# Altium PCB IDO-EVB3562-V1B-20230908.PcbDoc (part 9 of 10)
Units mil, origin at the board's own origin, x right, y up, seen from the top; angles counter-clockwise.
Board outline 5314.96 x 3543.31 mil, 4 copper layers (TOP, L2-VCC, L3-GND, BOTTOM), stack 28.8 mil thick; 747 components, 560 nets, 2514 pads, 1964 vias.
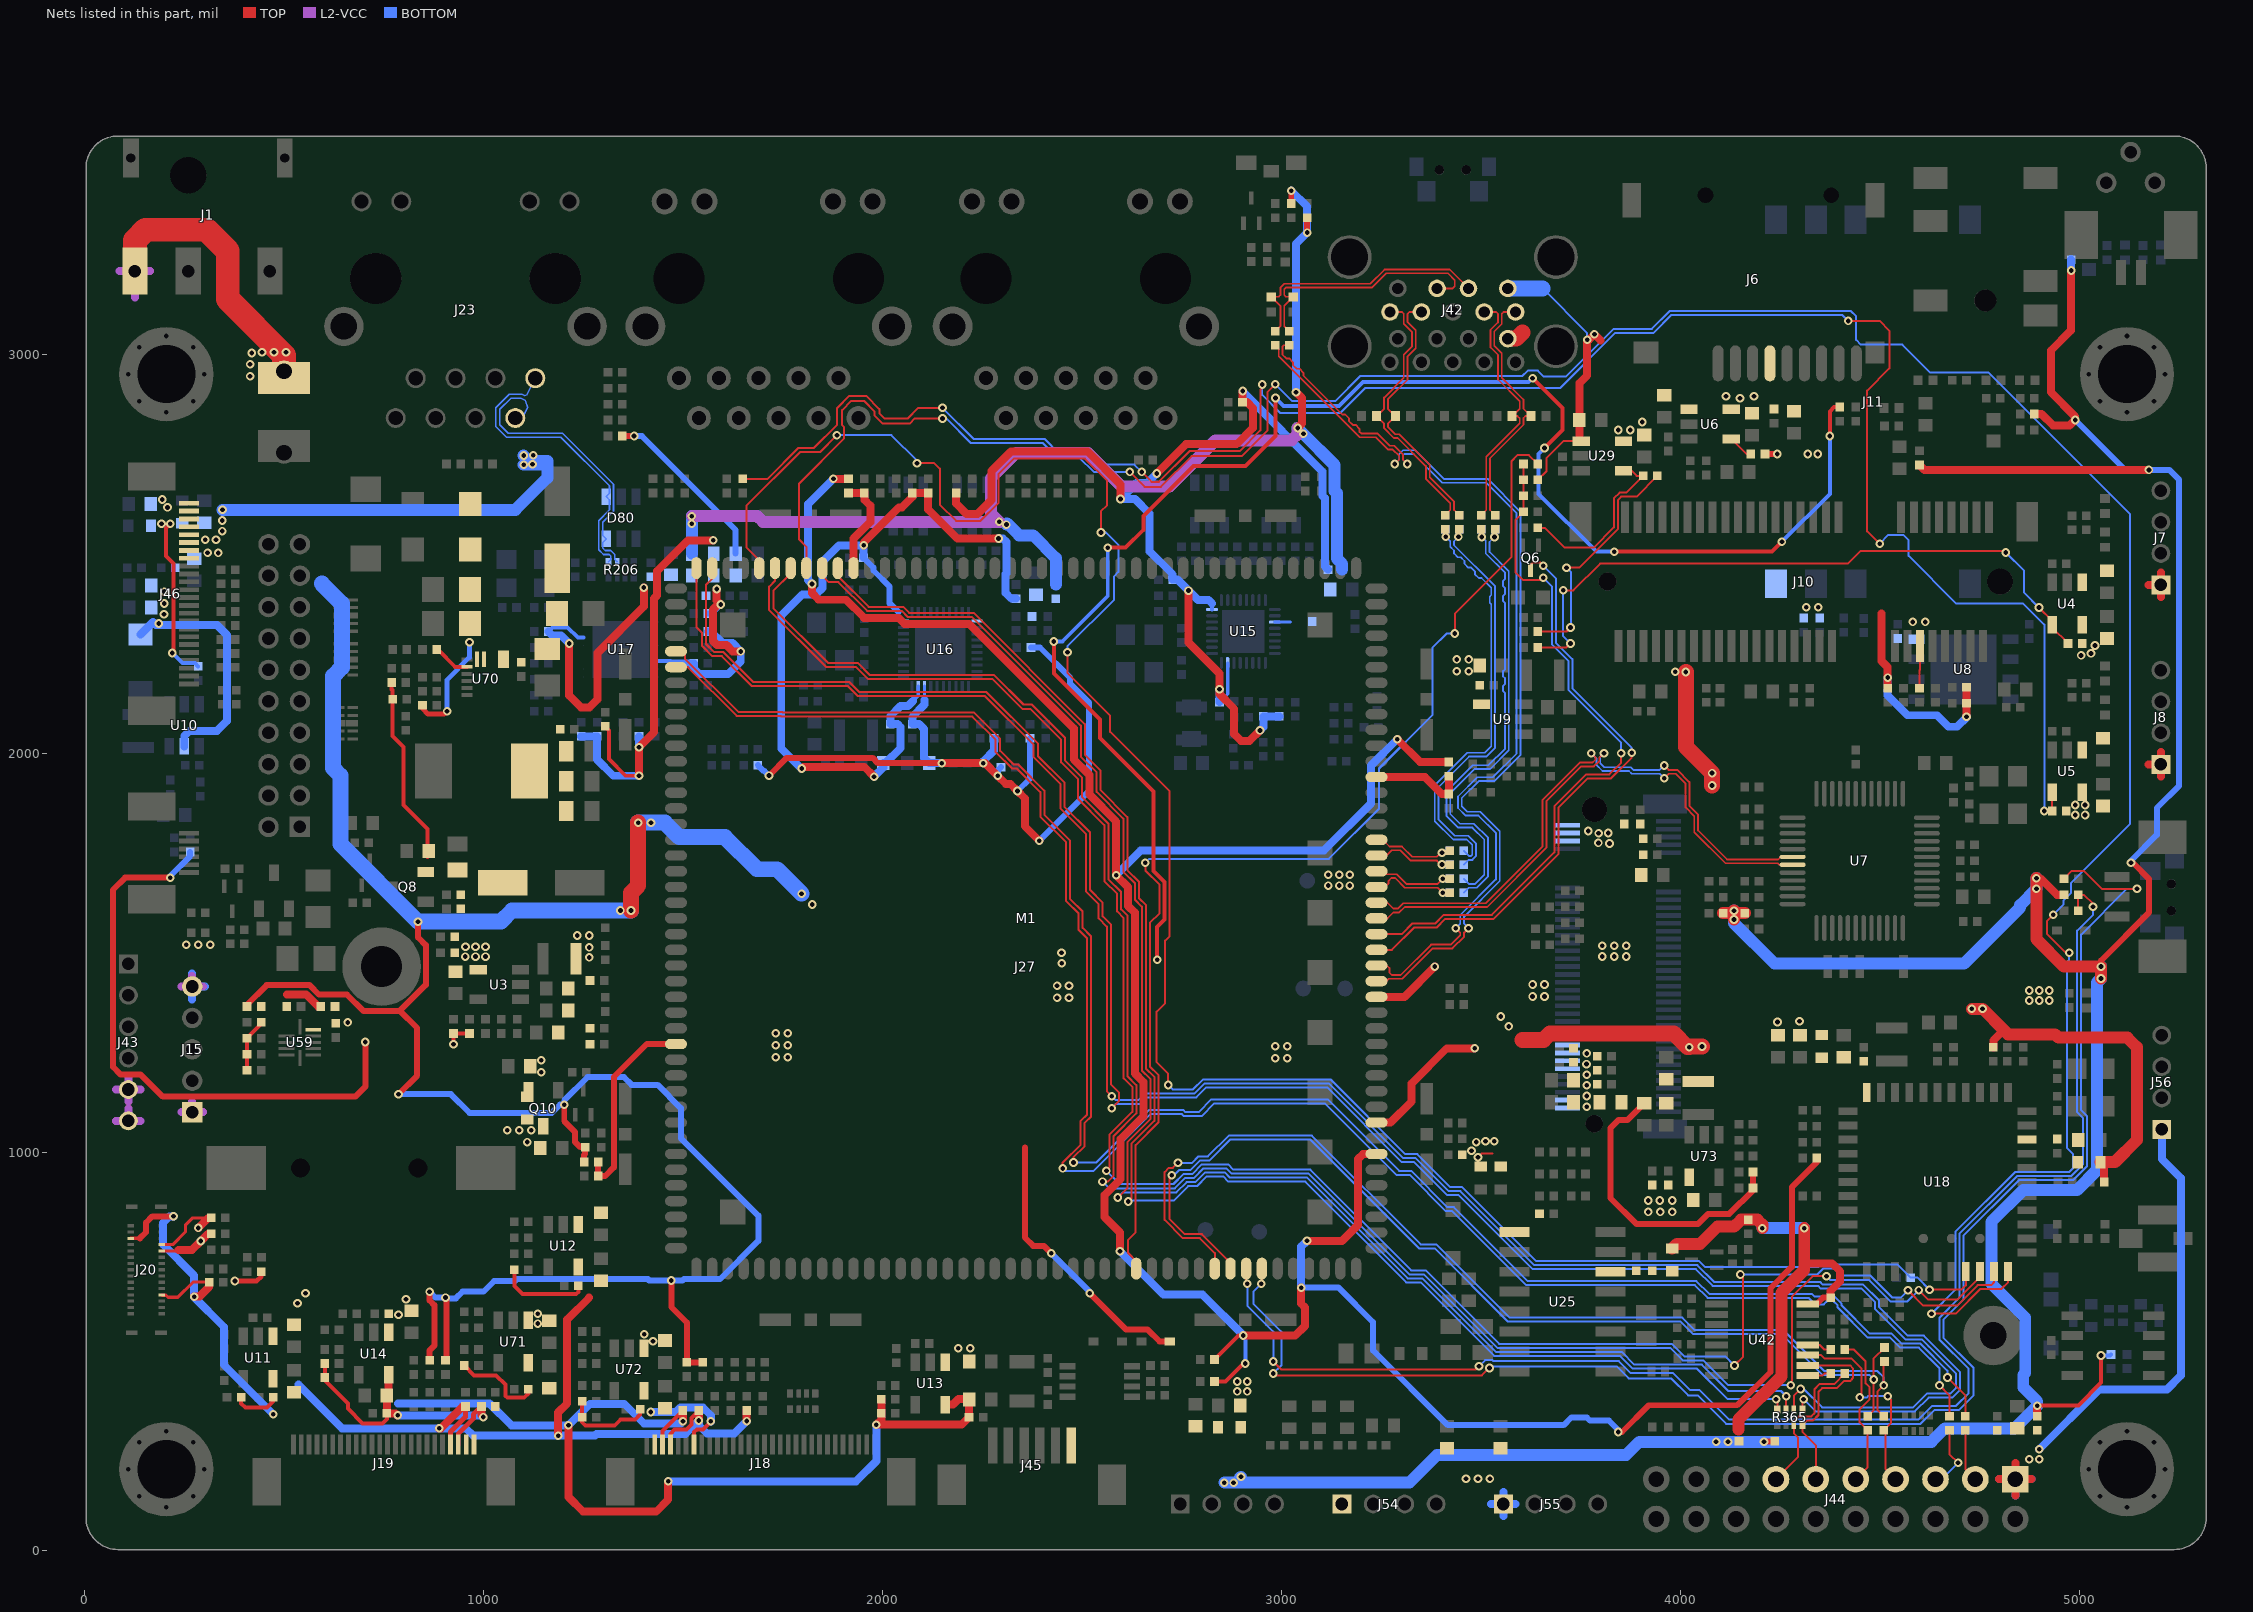
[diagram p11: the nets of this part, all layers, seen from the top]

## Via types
v1: diameter 21.65, hole 11.81, TOP to BOTTOM, 1964 vias

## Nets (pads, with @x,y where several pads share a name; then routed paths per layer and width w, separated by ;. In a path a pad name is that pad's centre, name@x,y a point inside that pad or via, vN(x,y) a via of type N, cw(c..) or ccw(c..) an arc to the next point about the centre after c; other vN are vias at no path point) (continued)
TXN: D80.6 J23.2 R206.6 | length 766.2
  BOTTOM w4: J23.2@1080,2840 1087.2,2836.4 1097.4,2839.8 1110.6,2866.2 1104.43,2884.69 1094.13,2889.85 1068.85,2889.85 1041,2862 1041,2823 1062,2802 1198.16,2802 1326,2674.14 1326,2606 1298.79,2578.79 1298.79,2545.66 D80.6@1307.6,2536.85 1298.79,2528.04 1298.79,2514.21 1305,2508 1319.47,2508 1329.33,2498.14 1329.33,2485.51 R206.6@1335.16,2479.68
TXP: D80.1 J23.1 R206.5 | length 766.1
  BOTTOM w4: J23.1@1130,2940 1109.03,2898.05 1103.66,2896.26 1096.49,2899.85 1064.7,2899.85 1031,2866.14 1031,2818.86 1057.86,2792 1194.02,2792 1316,2670 1316,2651.55 D80.1@1307.6,2643.15 1316,2634.75 1316,2610.14 1288.79,2582.93 1288.79,2510.07 1300.86,2498 1315.33,2498 1319.33,2494 1319.33,2485.51 R206.5@1313.5,2479.68
UART0_RX_M0_DEBUG: M1.165 R261.1 R463.1 | length 3705.9
  TOP w5: M1.165@2912.01,707.87 2912.01,672.99 v1(2915,670) ; v1(2980,475) 3000,455 3487.58,455 v1(3495.57,462.99) ; R463.1@4997.72,1605 R261.1@4997.72,1645 5012,1645 5035,1622 v1(5035,1615)
  BOTTOM w5: v1(2915,670) 2915,615 2980,550 v1(2980,475) ; v1(3495.57,462.99) 3511.18,478.6 3529.25,478.6 3532.05,475.8 3846.18,475.8 3876.13,445.85 3982.36,445.85 4024.11,404.1 4047.98,404.1 4122.62,329.46 4596.99,329.46 4631.52,364 4691.47,364 4723.24,395.77 4723.24,456.76 4650,530 4650,585 4700,635 4700,795 4845,940 4980,940 5010,970 5010,1085 4995,1100 4995,1555 5035,1595 v1(5035,1615)
UART0_TX_M0_DEBUG: M1.166 R464.1 | length 3983.1
  TOP w5: v1(2950,670) 2951.38,671.38 M1.166@2951.38,707.87 ; v1(2980,445) 2985,440 3503.12,440 v1(3521.89,458.77) ; R464.1@4962.28,1685 4982.13,1704.85 5012.15,1704.85 5057,1660 v1(5145,1660)
  BOTTOM w5: v1(2950,670) 2930,650 2930,620 3000,550 3000,465 v1(2980,445) ; v1(3521.89,458.77) 3525.92,462.8 3840.79,462.8 3870.74,432.85 3976.98,432.85 4019.91,389.92 4043.78,389.92 4115.23,318.46 4602.38,318.46 4636.91,353 4698.85,353 4735,389.14 4735,460 4660,535 4660,580 4710,630 4710,790 4850,930 4985,930 5020,965 5020,1090 5005,1105 5005,1545 5120,1660 v1(5145,1660)
UART3_CTSN_M1: M1.82 R239.2 U18.41 | length 5430.7
  TOP w5: M1.82@1691.54,2463.78 1691.54,2483.46 1659,2516 1659,2620.14 1793.86,2755 1844.24,2755 v1(1886.05,2796.81) ; v1(2087,2727) 2130,2727 2144.04,2712.96 2144.04,2622.96 2184.72,2582.28 2246.02,2582.28 2291.46,2627.71 2291.46,2700.27 2329.68,2738.5 2507.42,2738.5 2563.5,2682.42 2563.5,2621.37 2548,2605.87 v1(2548,2553) ; v1(2464,2253) 2464,2201.28 2479.64,2185.64 2571,2094.28 2571,2053.19 2720,1904.19 2720,1541 2708.8,1529.8 2708.8,1373.29 2687.67,1352.16 2687.67,1225.33 2716.34,1196.66 v1(2716.34,1168) ; v1(4625,655) 4705,655 4715.87,665.87 U18.41@4715.87,700.59
  BOTTOM w5: v1(1886.05,2796.81) 1886.34,2797.1 2022.4,2797.1 2087,2732.5 v1(2087,2727) ; v1(2464,2253) 2464,2268.07 2580.85,2384.91 2580.85,2443.38 2591.68,2454.21 2591.68,2522.18 2560.86,2553 v1(2548,2553) ; v1(2716.34,1168) 2727.42,1156.92 2778.77,1156.92 2803.92,1182.07 3123.36,1182.07 3310.43,995 3341.15,995 3423.98,912.17 3453.15,912.17 3638.65,726.67 4047.34,726.67 4061.8,712.21 4346.73,712.21 4352.74,718.22 4544.5,718.22 R239.2@4577.72,685 4595,685 v1(4625,655)
UART3_RTSN_M1: M1.79 U18.44 | length 6932.5
  TOP w5: M1.79@1809.65,2463.78 1809.65,2517.35 1791,2536 1791,2675.84 1904.38,2789.22 1904.38,2816.62 1899,2822 1899,2860 1922,2883 1954,2883 1980,2857 1980,2847.16 2000.98,2826.17 2068.17,2826.17 2081,2839 v1(2150.67,2839) ; v1(2620,2705) 2657.36,2667.64 2698.24,2667.64 2775.09,2744.49 2900.75,2744.49 2965,2808.74 2965,2904.49 v1(2985.25,2924.75) ; v1(4630,595) 4690.86,595 4752.53,656.67 4804.67,656.67 4822.17,674.17 U18.44@4822.17,700.59 ; v1(4935.17,1594.83) 4920,1579.66 4920,1546.32 4966.32,1500 v1(4975,1500)
  BOTTOM w5: v1(2150.67,2839) 2159.65,2839 2221.15,2777.5 2402.5,2777.5 2439,2741 2494,2741 2530,2705 v1(2620,2705) ; v1(2985.25,2924.75) 3027.33,2882.67 3134.98,2882.67 3197.72,2945.41 3604.41,2945.41 3618,2959 3643,2959 3658,2944 3713.39,2944 3833.04,3063.66 3929.09,3063.66 3973.76,3108.33 4427.67,3108.33 4441,3095 4441,3036 4453,3024 4557,3024 4627,2954 4773,2954 5128,2599 5128,1823 4980,1675 4980,1650 4961.15,1631.15 4961.15,1620.82 v1(4935.17,1594.83) ; v1(4630,595) 4690,655 4690,800 4840,950 4975,950 4985,960 4985,995 4970,1010 4970,1476.67 4975,1481.67 v1(4975,1500)
UART3_RX_M1: M1.80 U18.42 | length 4991.7
  TOP w5: M1.80@1770.28,2463.78 1770.28,2450.32 1726.69,2406.73 1726.69,2363.31 1863.67,2226.33 1937.84,2226.33 1967.84,2196.33 2271.24,2196.33 2279.53,2196.33 2353.86,2122 2374.35,2122 2458.33,2038.02 2458.33,2013.45 2458.33,1981.16 2500,1939.48 2500,1890.46 2566.74,1823.72 2566.74,1683.48 2598.35,1651.88 2598.35,1608.65 2615,1592 2615,1189.5 2636.67,1167.82 2636.67,1096.88 2580,1040.21 2580,941 2565,926 v1(2552,926) ; v1(4276.95,415.73) 4276.95,423.95 4280,427 4280,637 4331.89,688.89 v1(4366.86,688.89) ; v1(4597.81,654) 4621.81,630 4695,630 4751.3,686.3 U18.42@4751.3,700.59
  BOTTOM w5: v1(2552,926) 2569,909 2733.01,909 2758.47,934.46 2780.49,934.46 2804.99,958.96 2862.57,958.96 2875.68,945.85 3068.86,945.85 3321.14,693.57 3357.6,693.57 3541.96,509.22 3974.87,509.22 4006.08,478 4057.92,478 4120.19,415.73 v1(4276.95,415.73) ; v1(4366.86,688.89) 4376.75,679 4473.86,679 4526.86,626 4569.81,626 v1(4597.81,654)
UART3_TX_M1: M1.81 U18.43 | length 4962.4
  TOP w5: M1.81@1730.91,2463.78 1730.91,2431.91 1716.33,2417.33 1716.33,2358.67 1858.67,2216.33 1933.69,2216.33 1963.69,2186.33 2275.39,2186.33 2350.71,2111 2371.21,2111 2448.33,2033.88 2448.33,2017.6 2448.33,1985.3 ; 2448.32,1985.3 2448.32,1977.02 2490,1935.34 2490,1886.32 2556.74,1819.57 2556.74,1679.34 2588.35,1647.74 2588.35,1603.16 2605,1586.5 2605,1185 2626.67,1163.33 2626.67,1101.03 2570,1044.36 2570,961.33 v1(2561.67,953) ; v1(4136,465) 4158,487 4158,686 v1(4151,693) ; v1(4571.16,653.33) 4609.49,615 4694.14,615 4745.82,666.67 4779.67,666.67 4786.73,673.73 U18.43@4786.73,700.59
  BOTTOM w5: v1(2561.67,953) 2594.67,920 2729.87,920 2754.33,944.46 2776.35,944.46 2800.84,968.96 2866.72,968.96 2879.82,955.85 3073.01,955.85 3325.28,703.57 3361.75,703.57 3546.1,519.22 3979.01,519.22 4010.22,488 4113,488 v1(4136,465) ; v1(4151,693) 4343,693 4358,708 4386,708 4403.43,690.57 4476.43,690.57 4531,636 4553.84,636 v1(4571.16,653.33)
UART4_RX: J44.5 R369.2 | length 163.7
  TOP w5: R369.2@4675,302.28 4675,243.03 v1(4696.67,221.35)
  BOTTOM w5: J44.5@4640,180 4655.32,180 v1(4696.67,221.35)
UART4_RX_M0: M1.92 R369.1 | length 4769.7
  TOP w5: M1.92@1482.87,2215.75 1512.28,2215.75 1634.7,2093.33 1745,2093.33 1746.65,2091.67 2225.75,2091.67 2284,2033.43 2284,2002.69 2325.19,1961.5 2336.56,1961.5 2396,1902.05 2396,1841.03 2460.74,1776.29 2460.74,1629.26 2491.69,1598.31 2491.69,1557.31 2513,1536 2513,1094 2497,1078 2497,1018.86 2452,973.86 v1(2452,959) ; v1(4650,415) 4675,390 R369.1@4675,337.72
  BOTTOM w5: v1(2452,959) 2459,952 2529,952 2673,1096 2749.86,1096 2755.59,1090.26 2800.26,1090.26 2832.07,1122.07 3109.07,1122.07 3288.43,942.72 3321.58,942.72 3412.29,852 3428.47,852 3613.79,666.67 4036.62,666.67 4068.95,634.35 4321.73,634.35 4337.76,618.32 4360.43,618.32 4368.76,626.64 4383.95,626.64 4394.68,615.91 4394.68,610.32 4470.33,534.67 4526.04,534.67 4551.15,509.57 4598.25,509.57 4650,457.82 v1(4650,415)
UART4_TX: J44.3 R368.2 | length 132.6
  TOP w5: R368.2@4715,302.28 4715,205 J44.3@4740,180
UART4_TX_M0: M1.91 R368.1 | length 4770.7
  TOP w5: M1.91@1482.87,2255.12 1499.88,2255.12 1505,2250 1505,2237.17 1638.85,2103.33 1749.14,2103.33 1750.8,2101.67 2229.9,2101.67 2295,2036.57 2295,2005.83 2329.33,1971.5 2332.41,1971.5 2340.7,1971.5 2406,1906.2 2406,1845.17 2470.74,1780.43 2470.74,1634.26 2502,1603 2502,1562 2523,1541 2523,1089 2507,1073 2507,1014.72 2479,986.72 v1(2479,974) ; v1(4670,435) 4715,390 R368.1@4715,337.72
  BOTTOM w5: v1(2479,974) 2536.86,974 2668.86,1106 2754,1106 2759.74,1100.26 2792.83,1100.26 2824.64,1132.07 3116.64,1132.07 3295.72,953 3325.44,953 3416.27,862.17 3432.44,862.17 3617.94,676.67 4040.77,676.67 4073.09,644.35 4330,644.35 4337.02,637.33 4387.41,637.33 4404.68,620.05 4404.68,615.32 4475.33,544.67 4530.19,544.67 4555.29,519.57 4602.4,519.57 4670,451.96 v1(4670,435)
UART6_RX: J44.9 R371.2 R1167.1 | length 394.9
  TOP w5: R1167.1@4412.72,505 4435,505 4465,475 4465,420 4475,410 4475,380 4450,355 4450,322.28 R371.2@4470,302.28 4470,210 J44.9@4440,180
UART6_RX_: R1167.2 U42.12 | length 62.3
  TOP w5: U42.12@4319.7,516.34 4349.66,516.34 4361,505 R1167.2@4377.28,505
UART6_RX_M0: M1.164 R371.1 R1208.1 | length 2560.2
  TOP w5: v1(2725.79,941.84) 2720.03,936.08 2720.03,831.69 2757.71,794 2801,794 2872.64,722.36 M1.164@2872.64,707.87 ; R371.1@4470,337.72 4485.01,352.73 v1(4485.01,429.99) 4485.01,482.73 R1208.1@4512.28,510
  BOTTOM w5: v1(2725.79,941.84) 2731.08,941.84 2743.7,954.46 2772.21,954.46 2796.7,978.96 2820.17,978.96 2872.66,1031.44 3072.41,1031.44 3345.28,758.57 3384.53,758.57 3568.36,574.75 4001.27,574.75 4031.66,544.35 4253.56,544.35 4356.34,441.57 4473.43,441.57 v1(4485.01,429.99)
UART6_TX: J44.7 R370.2 U42.11 | length 526.1
  TOP w5: U42.11@4319.7,490.74 4353.26,490.74 4362,482 4430,482 4455,457 4455,390 v1(4450,385) ; v1(4520.11,388) 4528.35,379.76 4528.35,320.63 R370.2@4510,302.28 4515,297.28 4515,205 J44.7@4540,180
  BOTTOM w5: v1(4450,385) 4468.33,385 4471.33,388 v1(4520.11,388)
UART6_TX_M0: M1.163 R370.1 R1207.1 | length 2581
  TOP w5: v1(2741,973) 2728.17,960.17 2718.2,960.17 2707.47,949.44 2707.47,830.11 2753.57,784 2761.85,784 2796,784 2833.27,746.73 M1.163@2833.27,707.87 ; R370.1@4510,337.72 4495.01,352.71 4495.01,400.01 v1(4510,415) 4510,472.72 R1207.1@4512.28,475
  BOTTOM w5: v1(2741,973) 2776.6,973 2792.56,988.96 2816.03,988.96 2868.51,1041.44 3076.56,1041.44 3349.43,768.57 3388.68,768.57 3572.51,584.75 4005.41,584.75 4035.8,554.35 4257.7,554.35 4360.49,451.57 4493.43,451.57 4510,435 v1(4510,415)
UART8_RX: J44.13 R365.7 R1166.1 | length 385
  TOP w5: J44.13@4240,180 4295,235 4295,285.03 4284.84,295.19 R365.7@4284.84,315.31 4284.84,324.84 4297.33,337.33 4329.01,337.33 4336.67,345 4336.67,405.67 4349,418 4385.72,418 R1166.1@4412.72,445
UART8_RX_: R1166.2 U42.9 | length 59.8
  TOP w5: U42.9@4319.7,439.54 4356.54,439.54 4362,445 R1166.2@4377.28,445
UART8_RX_M0: M1.85 R365.2 | length 5106.9
  TOP w5: M1.85@1573.42,2463.78 1573.42,2437.42 1557.93,2421.93 1557.93,2273.58 1578.18,2253.33 1601.73,2253.33 1676.74,2178.33 1917.27,2178.33 1942.27,2153.33 2260.96,2153.33 2390,2024.29 2390,1992.91 2456,1926.91 2456,1865.89 2520.74,1801.14 2520.74,1656.91 2552.35,1625.31 2552.35,1590.65 2573.25,1569.75 2573.25,1168.75 2593.33,1148.67 2593.33,1128.33 v1(2575,1110) ; R365.2@4284.84,354.69 4284.84,389.11 v1(4301.78,406.05)
  BOTTOM w5: v1(2575,1110) 2585,1120 2645.14,1120 2662.06,1136.92 2787.05,1136.92 2812.21,1162.07 3115.07,1162.07 3302.14,975 3332.87,975 3415.7,892.17 3444.87,892.17 3630.36,706.67 4039.05,706.67 4081.38,664.35 4345.65,664.35 4351.44,658.57 4453.85,658.57 4488.71,623.71 4488.71,606.29 4565.44,529.57 4606.54,529.57 4623.05,513.05 4691.74,444.37 4691.74,408.82 4677.42,394.5 4618.48,394.5 4584.08,360.1 4355.7,360.1 4309.75,406.05 v1(4301.78,406.05)
UART8_TX: J44.11 R365.8 U42.10 | length 499.6
  TOP w5: U42.10@4319.7,465.14 4425.86,465.14 4433,458 4433,434 4431.07,432.07 4431.07,431.04 4426.68,426.65 4411.65,426.65 4393,408 4356,408 4346.67,398.67 4346.67,340.86 4333.15,327.33 4318.52,327.33 R365.8@4306.5,315.31 4306.5,298.5 4340,265 J44.11@4340,180
UART8_TX_M0: M1.86 R365.1 | length 5052.5
  TOP w5: M1.86@1534.06,2463.78 1534.06,2315.7 1547.93,2301.82 1547.93,2269.43 1574.03,2243.33 1597.59,2243.33 1672.59,2168.33 1913.12,2168.33 1938.12,2143.33 2256.82,2143.33 2379,2021.14 2379,2012.86 2379,1989.77 2446,1922.77 2446,1861.74 2510.74,1797 2510.74,1652.77 2542.35,1621.17 2542.35,1585.65 2563,1565 2563,1152 v1(2575,1140) ; R365.1@4306.5,354.69 4306.5,377.62 v1(4309.38,380.5)
  BOTTOM w5: v1(2575,1140) 2585,1130 2641,1130 2657.92,1146.92 2782.91,1146.92 2808.07,1172.07 3119.22,1172.07 3306.29,985 3337.01,985 3419.84,902.17 3449.01,902.17 3634.51,716.67 4043.2,716.67 4085.52,674.35 4350.65,674.35 4356.43,668.57 4457.99,668.57 4498.71,627.85 4498.71,611.29 4570.43,539.57 4610.68,539.57 4701.74,448.51 4701.74,404.68 4681.56,384.5 4622.62,384.5 4588.22,350.1 4339.78,350.1 v1(4309.38,380.5)
UART9_RX_M1: M1.77 R365.4 | length 3996.7
  TOP w5: M1.77@1888.39,2463.78 1888.39,2444.14 1965.86,2366.67 2052.22,2366.67 2067.22,2351.67 2228.74,2351.67 2507.5,2072.92 2507.5,1995.63 2547,1956.13 2547,1907.1 2614.31,1839.79 2614.31,1706.55 2643.35,1677.51 2643.35,1636.65 2660.5,1619.5 2660.5,1209.5 2681.67,1188.33 2681.67,1078.24 2625,1021.57 2625,951.36 2625,884.33 v1(2616.67,876) ; v1(4240.41,380.36) 4243.5,377.26 R365.4@4243.5,354.69
  BOTTOM w5: v1(2616.67,876) 2617,876 2619.17,878.17 2730.47,878.17 2766.76,914.46 2788.78,914.46 2813.27,938.96 2854.29,938.96 2867.39,925.85 3060.58,925.85 3312.86,673.57 3349.32,673.57 3533.67,489.22 3849.03,489.22 3880.89,457.35 4042.16,457.35 4119.15,380.36 v1(4240.41,380.36)
UART9_TX_M1: M1.78 R365.3 | length 4079.8
  TOP w5: M1.78@1849.02,2463.78 1849.02,2444.98 1865.28,2428.72 1889.67,2428.72 1961.71,2356.67 2048.08,2356.67 2063.08,2341.67 2224.6,2341.67 2497.5,2068.78 2497.5,1991.48 2537,1951.98 2537,1902.96 2604.31,1835.65 2604.31,1702.4 2633.35,1673.37 2633.35,1632.51 2650.5,1615.36 2650.5,1204.5 2671.67,1183.33 2671.67,1082.39 2615,1025.72 2615,955.51 2615,911 v1(2590,886) ; R365.3@4265.16,354.69 4265.16,386.9 v1(4266.01,387.76)
  BOTTOM w5: v1(2590,886) 2603,899 2737.15,899 2762.62,924.46 2784.64,924.46 2809.13,948.96 2858.43,948.96 2871.53,935.85 3064.72,935.85 3317,683.57 3353.46,683.57 3537.82,499.22 3853.17,499.22 3885.03,467.35 4054.42,467.35 4120.77,401 4252.77,401 v1(4266.01,387.76)
USB20_HOST1_DM: M1.22 U7.30 | length 1496.4
  TOP w4.5: M1.22@3238.78,1585.83 3266.34,1585.83 3281.27,1600.76 3295.76,1600.76 3309.34,1614.34 3516.36,1614.34 3664.68,1762.66 3664.68,1879.31 3752.12,1966.75 3783.75,1966.75 3797.15,1980.15 3797.15,1988.15 v1(3809,2000) ; v1(3960,1969) 3971,1958 3992.67,1958 4023.12,1927.55 4023.12,1867.82 4045,1845.94 4045,1806 4117.5,1733.5 4245.45,1733.5 4251.75,1739.8 U7.30@4281.7,1739.8
  BOTTOM w4.5: v1(3809,2000) 3799.5,1990.5 3799.5,1974.5 3809.25,1964.75 3875.69,1964.75 3882.44,1958 3949,1958 v1(3960,1969)
USB20_HOST1_DP: M1.23 U7.31 | length 1496.1
  TOP w4.5: M1.23@3238.78,1625.2 3266.34,1625.2 3281.27,1610.26 3291.83,1610.26 3305.41,1623.84 3512.42,1623.84 3655.18,1766.6 3655.18,1883.24 3748.19,1976.25 3779.81,1976.25 3787.65,1984.08 3787.65,1989.51 3783.27,1993.88 3783.27,1994.07 v1(3777.35,2000) ; v1(3960,1937.35) 3965.89,1943.23 3966.47,1943.23 3971.74,1948.5 3988.73,1948.5 4013.62,1923.61 4013.62,1863.88 4035.5,1842 4035.5,1802.06 4113.56,1724 4245,1724 4248.8,1720.2 U7.31@4281.7,1720.2
  BOTTOM w4.5: v1(3777.35,2000) 3777.35,1999.56 3790,1986.9 3790,1970.57 3805.32,1955.25 3871.75,1955.25 3878.5,1948.5 3948.64,1948.5 3952.14,1945 3952.35,1945 v1(3960,1937.35)
USB30_OTG0_DM: M1.18 R247.1 | length 2381.8
  TOP w4.5: R247.1@2985,3022.28 2993.6,3013.68 2993.6,2995.16 3196.66,2792.1 3236.9,2792.1 3268,2761 3279.56,2761 3295.5,2745.06 3295.5,2736.08 v1(3284.42,2725) ; M1.18@3238.78,1428.35 3263.35,1428.35 3269.35,1434.35 3303.35,1434.35 3379.5,1510.5 3428.94,1510.5 3458.25,1539.81 3458.25,1550.19 v1(3469.33,1561.27)
  BOTTOM w4.5: v1(3284.42,2725) 3295.5,2736.08 3295.5,2749.94 3305.06,2759.5 3335.5,2759.5 3407.5,2687.5 3517.5,2687.5 3599.5,2605.5 3599.5,1995.24 3534.26,1930 3495,1930 3452.48,1887.48 3452.48,1866.52 3466,1853 3498.44,1853 3547.5,1803.94 3547.5,1679.49 3458.25,1590.24 3458.25,1572.34 v1(3469.33,1561.27)
USB30_OTG0_DP: M1.19 R248.1 | length 2376.7
  TOP w4.5: R248.1@3020,3022.28 3006.28,3022.28 3003.1,3019.1 3003.1,2999.1 3012.65,2989.55 3019.72,2989.55 3029.26,2980 3029.26,2972.93 3038.81,2963.39 3045.88,2963.39 3055.43,2953.84 3055.43,2946.77 3153.21,2848.99 3160.28,2848.99 3169.83,2839.44 3169.83,2832.37 3179.37,2822.83 3186.44,2822.83 3195.99,2813.28 3195.99,2806.21 3200.6,2801.6 3240.84,2801.6 3271.94,2770.5 3283.5,2770.5 3305,2749 3305,2736.08 v1(3316.08,2725) ; M1.19@3238.78,1467.72 3264.66,1467.72 3271.22,1461.15 3271.22,1449.78 3277.15,1443.85 3299.41,1443.85 3375.56,1520 3425,1520 3448.75,1543.75 3448.75,1550.19 v1(3437.67,1561.27)
  BOTTOM w4.5: v1(3316.08,2725) 3305,2736.08 3305,2746 3309,2750 3331.56,2750 3403.56,2678 3513.56,2678 3590,2601.56 3590,1999.18 3530.32,1939.5 3491.06,1939.5 3442.98,1891.41 3442.98,1862.59 3462.06,1843.5 3494.5,1843.5 3538,1800 3538,1683.42 3448.75,1594.17 3448.75,1572.34 v1(3437.67,1561.27)
USB30_OTG0_ID: M1.20 Q6.3 | length 1530.9
  TOP w5: M1.20@3238.78,1507.09 3277.09,1507.09 3333,1563 3389.71,1563 3411.3,1584.59 3532.14,1584.59 3694.43,1746.88 3694.43,1862.88 3768.55,1937 3826.61,1937 3878.5,1988.89 v1(3878.5,2000.66) ; Q6.3@3625,2458.5 3625,2472.37 3630,2477.37 3649.36,2477.37 v1(3656.73,2470)
  BOTTOM w5: v1(3656.73,2470) 3688.35,2438.39 3688.35,2276.65 3729.59,2235.41 3729.59,2162.8 3878.5,2013.89 v1(3878.5,2000.66)
USB30_OTG0_SSRXN/PCIE20_RXDN: M1.27 R406.1 R1204.1 | length 225.7
  TOP w4.5: M1.27@3238.78,1782.68 3254.66,1782.68 3271.38,1765.96 3302.47,1765.96 3328.19,1740.25 3390.27,1740.25 3400.02,1750 v1(3403,1750) R406.1@3422.28,1755
  BOTTOM w4.5: v1(3403,1750) R1204.1@3422.28,1755
USB30_OTG0_SSRXP/PCIE20_RXDP: M1.26 R405.1 R1203.1 | length 223.7
  TOP w4.5: M1.26@3238.78,1743.31 3263.31,1743.31 3276.46,1756.46 3298.54,1756.46 3324.25,1730.75 3390.27,1730.75 3400.02,1721 v1(3403,1721) 3404,1720 R405.1@3422.28,1720
  BOTTOM w4.5: v1(3403,1721) 3404,1720 R1203.1@3422.28,1720
USB30_OTG0_SSTXN/PCIE20_TXDN: C354.2 M1.25 R1205.1 | length 219.2
  TOP w4.5: M1.25@3238.78,1703.94 3253.06,1703.94 3260.5,1696.5 3289.5,1696.5 3313.75,1672.25 3392.25,1672.25 v1(3405,1685) C354.2@3422.28,1685
  BOTTOM w4.5: v1(3405,1685) R1205.1@3422.28,1685
USB30_OTG0_SSTXP/PCIE20_TXDP: C353.2 M1.24 R1206.1 | length 228.9
  TOP w4.5: M1.24@3238.78,1664.57 3259.57,1664.57 3269,1674 3269,1680 3276,1687 3285.56,1687 3309.81,1662.75 3392.25,1662.75 v1(3405,1650) C353.2@3422.28,1650
  BOTTOM w4.5: v1(3405,1650) R1206.1@3422.28,1650
USB30_OTG0_VBUSDET: C347.2 M1.21 R253.2 R353.2 R445.1 | length 1763.5
  TOP w5: M1.21@3238.78,1546.46 3302.31,1546.46 3328.86,1573 3385.56,1573 3407.16,1594.59 3527.99,1594.59 3684.43,1751.03 3684.43,1867.02 3764.41,1947 3822.47,1947 3851.85,1976.38 v1(3851.85,2000) ; R353.2@3607.28,2725 R445.1@3607.28,2685 R253.2@3607.28,2645 C347.2@3607.28,2605 3587.33,2585.05 3587.33,2452.67 3605.73,2434.27 3650.91,2434.27 v1(3656.63,2440)
  BOTTOM w5: v1(3656.63,2440) 3678.35,2418.29 3678.35,2272.51 3719.59,2231.27 3719.59,2158.66 3851.85,2026.39 v1(3851.85,2000)
USB_HOST2_PWREN_H: R1168.1 U6.4 | length 64.7
  TOP w5: U6.4@4128.15,2787.6 4165.75,2750 R1168.1@4177.28,2750
USB_HOST3_PWREN_H: R430.1 R450.1 U4.4 | length 1671.7
  TOP w5: R430.1@3642.72,2265 3715,2265 v1(3725,2275) ; v1(3706.67,2408.33) 3732.47,2408.33 3799.14,2475 4420,2475 4451.67,2506.67 4812.33,2506.67 v1(4816,2503) ; v1(4899.43,2365) 4932.6,2331.83 U4.4@4932.6,2321.85 4932.6,2314.68 R450.1@4972.28,2275
  BOTTOM w5: v1(3706.67,2408.33) 3706.67,2293.33 v1(3725,2275) ; v1(4816,2503) 4862.1,2456.9 4862.1,2402.33 v1(4899.43,2365)
USB_HOST4_PWREN_H: R451.1 R1082.1 U5.4 | length 5072.7
  TOP w5: R1082.1@1650,2687.72 1712.43,2687.72 1789.71,2765 1828.32,2765 1886.5,2823.18 1886.5,2865.18 1916.82,2895.5 1959.18,2895.5 1992.5,2862.18 1992.5,2852.34 2006.16,2838.67 2062.99,2838.67 2089.98,2865.65 v1(2150.67,2865.65) ; v1(2650,2705) 2674.86,2680.14 2693.07,2680.14 2769.91,2756.99 2895.57,2756.99 2947.7,2809.12 2947.7,2910.7 2952,2915 v1(2952,2924) ; v1(4421,3083.5) 4499.87,3083.5 4524.5,3058.87 4524.5,2964.32 4468.75,2908.57 4468.75,2556.25 v1(4500,2525) ; v1(4913,1855) R451.1@4932.28,1855 4932.6,1855.32 U5.4@4932.6,1901.85
  BOTTOM w5: v1(2150.67,2865.65) 2228.83,2787.5 2406.64,2787.5 2443.14,2751 2498.14,2751 2525.82,2723.33 2631.67,2723.33 v1(2650,2705) ; v1(2952,2924) 2952,2898 2997.33,2852.67 3147.41,2852.67 3210.15,2915.41 3698.94,2915.41 3837.18,3053.66 3933.24,3053.66 3977.91,3098.33 4406.17,3098.33 v1(4421,3083.5) ; v1(4500,2525) 4522,2547 4559.22,2547 4572.43,2533.79 4572.43,2494.33 4691.75,2375 4860,2375 4913,2322 v1(4913,1855)
USB_OTG: C261.1 J42.1 R445.2 U29.1 | length 739.8
  TOP w5: R445.2@3642.72,2685 3665,2707.28 3665,2740 3707.4,2782.4 U29.1@3751.85,2782.4
  TOP w20: U29.1@3751.85,2782.4 3747.44,2786.81 C261.1@3747.44,2835 3747.44,2927.44 3767,2947 v1(3767,3036) 3771,3036 v1(3785,3050) 3800,3035
  BOTTOM w5: 3655,3165 3767,3053 v1(3767,3036)
  BOTTOM w40: J42.1@3567.8,3165 3655,3165
USB_OTG_DET_GPIO0_C0_D: M1.158 R353.1 | length 2834.2
  TOP w5: M1.158@2636.42,707.87 2636.42,726.58 2616,747 2616,780 2635,799 2635,947.22 2635,1017.43 2691.67,1074.1 2691.67,1193.33 2670.5,1214.5 2670.5,1574.5 2695,1599 2695,1670 2659.17,1705.83 v1(2659.17,1725) ; v1(3435,2300) 3435,2350 3577.33,2492.33 3577.33,2732.33 3592,2747 3620.72,2747 R353.1@3642.72,2725
  BOTTOM w5: v1(2659.17,1725) 2669.17,1735 3119.14,1735 3245,1860.86 3245,1961.56 3378.75,2095.31 3378.75,2263.75 3415,2300 v1(3435,2300)
USB_OTG_DM: D37.2 J42.2 R247.2 | length 653.9
  TOP w4.5: R247.2@2985,3057.72 2997.75,3070.47 2997.75,3121.15 D37.2@2975,3143.9 2993.25,3143.9 2997.75,3148.4 2997.75,3166.44 3007.81,3176.5 3223.06,3176.5 3259.06,3212.5 3421.87,3212.5 J42.2@3469.37,3165
USB_OTG_DP: D38.2 J42.3 R248.2 | length 653.6
  TOP w4.5: R248.2@3020,3057.72 3007.25,3070.47 3007.25,3121.15 D38.2@3030,3143.9 3011.75,3143.9 3007.25,3148.4 3007.25,3162.5 3011.75,3167 3227,3167 3263,3203 3417.93,3203 3435,3185.93 3435,3170 3430,3165 J42.3@3390.63,3165
USB_OTG_PWREN: R352.1 R429.1 | length 607.5
  TOP w5: R429.1@3642.72,2305 3715,2305 v1(3725,2315) ; v1(3715,2465) 3747,2465 3843.7,2561.7 3843.7,2634.51 3852.19,2643 3890.72,2643 R352.1@3942.72,2695
  BOTTOM w5: v1(3715,2465) 3726.59,2453.41 3726.59,2316.59 v1(3725,2315)
USB_OTG_PWREN_H: R352.2 R456.1 U29.4 | length 456.8
  TOP w5: R456.1@3642.72,2565 3661,2565 3711,2515 3782.86,2515 3833.7,2565.84 3833.7,2638.65 3848.05,2653 3865.28,2653 R352.2@3907.28,2695 3891,2695 3878.4,2707.6 U29.4@3858.15,2707.6
USB_OTG_SSRXN: D42.2 J42.5 R410.2 | length 674
  TOP w4.5: J42.5@3272.52,3105.94 3302.64,3105.94 3307.14,3101.44 3307.14,3076.42 3327.5,3056.06 3327.5,3018.94 3307.14,2998.58 3307.14,2940.58 3257.75,2891.19 3257.75,2863.85 D42.2@3238.9,2845 3257.75,2826.15 3257.75,2814.25 3282,2790 3292,2790 3362.51,2719.49 3362.51,2687.49 3423.75,2626.25 3423.75,2609.47 R410.2@3411,2596.72
USB_OTG_SSRXP: D41.2 J42.6 R409.2 | length 674
  TOP w4.5: J42.6@3351.26,3105.94 3321.14,3105.94 3316.64,3101.44 3316.64,3080.36 3337,3060 3337,3015 3316.64,2994.64 3316.64,2936.64 3267.25,2887.25 3267.25,2863.85 D41.2@3286.1,2845 3267.25,2826.15 3267.25,2818.19 3285.94,2799.5 3295.94,2799.5 3372.01,2723.43 3372.01,2691.43 3433.25,2630.19 3433.25,2609.47 R409.2@3446,2596.72
USB_OTG_SSTXN: C346.1 D40.2 J42.8 | length 642.7
  TOP w4.5: C346.1@3501,2596.72 3513.75,2609.47 3513.75,2743.19 3597.75,2827.19 3597.75,2839.25 3592,2845 D40.2@3578.9,2845 3597.75,2863.85 3597.75,2882.25 3543.36,2936.64 3543.36,2998.2 3524.5,3017.06 3524.5,3060.94 3543.36,3079.8 3543.36,3101.44 3538.86,3105.94 J42.8@3508.74,3105.94
USB_OTG_SSTXP: C345.1 D39.2 J42.9 | length 643.3
  TOP w4.5: C345.1@3536.01,2596.72 3523.25,2609.47 3523.25,2739.25 3607.25,2823.25 3607.25,2840.25 3612,2845 D39.2@3626.1,2845 3607.25,2863.85 3607.25,2886.19 3552.86,2940.58 3552.86,3002.14 3534,3021 3534,3057 3552.86,3075.86 3552.86,3101.44 3557.36,3105.94 J42.9@3587.48,3105.94
USB_PCIE_RXN: R402.1 R410.1 R1204.2 | length 1069
  TOP w4.5: R410.1@3411,2561.28 3412.45,2559.83 v1(3412.45,2542.42)
  BOTTOM w4.5: R402.1@3411,2561.28 3411,2543.88 v1(3412.45,2542.42) 3423.53,2531.35 3423.53,2517.47 3433.07,2507.92 3433.07,2500.85 3442.62,2491.3 3449.69,2491.3 3459.24,2481.76 3459.24,2474.69 3468.78,2465.14 3475.86,2465.14 3485.4,2455.6 3485.4,2448.53 3494.95,2438.98 3502.02,2438.98 3526.5,2414.5 3526.5,2396.46 3522.5,2392.46 3522.5,2376.96 3526.5,2372.96 3526.5,2017.7 3509.62,2000.82 3466.73,2000.82 3384.98,1919.07 3384.98,1829.59 3431.06,1783.5 3465.06,1783.5 3478.5,1770.06 3478.5,1745.29 3475.21,1742 3470.72,1742 R1204.2@3457.72,1755
USB_PCIE_RXP: R401.1 R409.1 R1203.2 | length 1069.1
  TOP w4.5: v1(3444.11,2542.42) 3444.11,2559.39 R409.1@3446,2561.28
  BOTTOM w4.5: R401.1@3446,2561.28 3446,2544.32 v1(3444.11,2542.42) 3433.03,2531.35 3433.03,2521.4 3536,2418.43 3536,2013.77 3513.55,1991.32 3470.67,1991.32 3394.48,1915.13 3394.48,1833.52 3435,1793 3469,1793 3488,1774 3488,1741.35 3479.15,1732.5 3470.22,1732.5 R1203.2@3457.72,1720
USB_PCIE_TXN: C317.1 C346.2 R1205.2 | length 1137.5
  TOP w4.5: C346.2@3501,2561.28 3502.76,2559.52 v1(3502.76,2541.73)
  BOTTOM w4.5: R1205.2@3457.72,1685 3470.47,1672.25 3485.81,1672.25 3509,1695.44 3509,1783.56 3479.06,1813.5 3444.06,1813.5 3413.98,1843.59 3413.98,1903.43 3480.05,1969.5 3519.31,1969.5 3561,2011.19 3561,2150.25 3556,2155.25 3556,2168.75 3561,2173.75 3561,2187.25 3556,2192.25 3556,2205.75 3561,2210.75 3561,2376.25 3556,2381.25 3556,2394.75 3561,2399.75 3561,2413.25 3556,2418.25 3556,2431.75 3561,2436.75 3561,2452 3512.53,2500.47 3512.53,2531.97 v1(3502.76,2541.73) 3502.76,2559.52 C317.1@3501.01,2561.28
USB_PCIE_TXP: C319.1 C345.2 R1206.2 | length 1137.6
  TOP w4.5: v1(3534.42,2541.73) 3534.42,2559.69 C345.2@3536.01,2561.28
  BOTTOM w4.5: R1206.2@3457.72,1650 3470.47,1662.75 3489.75,1662.75 3518.5,1691.5 3518.5,1787.5 3483,1823 3448,1823 3423.48,1847.52 3423.48,1899.49 3483.99,1960 3523.25,1960 3570.5,2007.25 3570.5,2455.93 3522.03,2504.4 3522.03,2529.35 v1(3534.42,2541.73) 3536,2543.32 3536,2548 C319.1@3536.01,2561.28
USIM_CLK: J10.12 R55.1 | length 106.4
  TOP w5: R55.1@4600,2162.72 4600,2208 4601.3,2209.3 J10.12@4601.3,2268.6
VBAT_WL_1T1R: C176.2 C344.2 R241.2 U18.9
VCC1V2_DVP: C103.2 C104.2 C1023.2 C1030.2 C1048.2 J18.28 J20.22 R136.2 U13.5 | length 2613.8
  TOP w8: J20.22@193.98,752.24 232.3,752.24 235.06,755
  TOP w10: J18.28@1448.94,267.01 1448.94,301.22 C1023.2@1500,352.28
  TOP w20: 235.06,755 269.42,755 v1(291.62,777.2) 309.42,794.99 C1030.2@317.28,794.99 ; v1(1213,315) 1213,135.5 1250,98.5 1433,98.5 1463.2,128.7 v1(1463.2,174.54) ; v1(1500,325) C1023.2@1500,352.28 ; R136.2@1997.28,380 C1048.2@1997.28,344.99 1997.28,329.01 v1(1985,316.73) 2199.02,316.73 C104.2@2217.28,334.99 2217.28,379.83 C103.2@2217.44,380 2216.45,380.99 2190.99,380.99 2176.85,366.85 U13.5@2157.4,366.85
  BOTTOM w20: 785.4,370 1015,370 1070,315 v1(1213,315) 1267,369 1353,369 1402,320 1495,320 v1(1500,325) ; v1(1463.2,174.54) 1933.83,174.54 1985,225.71 v1(1985,316.73)
VCC1V5_DVP: C107.2 C108.2 C369.2 C1026.2 J19.3 R138.2 U14.5 | length 761.5
  TOP w10: R138.2@602.28,470 C369.2@602.28,435 602.28,427.72 660,370 660,357 697,320 747,320 757.72,330.72 C108.2@757.72,345.01
  TOP w12: J19.3@937.01,267.01 937.01,293.88 975,331.87 975,342.27 C1026.2@995.01,362.28
  TOP w20: U14.5@762.4,441.85 762.4,394.85 C107.2@757.56,390 757.72,389.84 C108.2@757.72,345.01 779.99,345.01 v1(785,340) ; C1026.2@995.01,362.28 995.01,340.39 v1(999.8,335.6)
  BOTTOM w20: v1(785,340) 995.4,340 v1(999.8,335.6)
VCC1V8_DVP: C100.2 C101.2 C1024.2 C1027.2 C1029.2 J18.27 J19.4 J20.24 R113.2 R134.2 R417.2 U12.5 | length 2493.1
  TOP w8: J20.24@193.98,767.99 221.17,767.99 252.83,799.64 252.83,816.56 271.26,834.99 C1029.2@310.25,834.99
  TOP w10: R134.2@1077.28,705 1077.28,664.72 1097.85,644.15 1232.15,644.15 1237.72,649.72 C101.2@1237.72,665 ; J18.27@1468.62,267.01 1468.62,293.62 1479,304 1508.45,304 1521,316.55 1521,333.28 C1027.2@1540,352.28
  TOP w12: v1(377,676.78) 377.17,676.96 431.95,676.96 442.72,687.72 R417.2@442.72,700 ; J19.4@917.32,267.01 917.32,298.24 955.01,335.92 C1024.2@955.01,362.28
  TOP w20: v1(285.12,809.87) 310.25,834.99 C1029.2@317.28,834.99 ; v1(889,307.61) 893.25,307.61 947.92,362.28 C1024.2@955.01,362.28 ; v1(1187.17,289.17) 1187.17,347.17 1210,370 1210,580 1265,635 ; v1(1540,327) C1027.2@1540,352.28 ; v1(1660,325.6) R113.2@1660,352.28
  BOTTOM w20: 536,417 645.39,307.61 v1(889,307.61) 955.9,307.61 974.34,289.17 v1(1187.17,289.17) 1280.17,289.17 1284,293 1506,293 v1(1540,327) 1540,315 1560,295 1629.4,295 v1(1660,325.6)
VCC2V8_DVP: C96.2 C98.2 C1028.2 J20.8 J20.25 R132.2 U11.5 | length 1082
  TOP w8: J20.25@116.03,783.74 138.74,783.74 ; J20.8@193.98,642 194.81,641.17 204,641.17 209.17,636 234,636 272,673.99 C1028.2@312.28,673.99
  TOP w10: R132.2@392.72,385 392.72,370.28 403,360 458,360 472.72,374.72 C98.2@472.72,385.01
  TOP w15: 138.74,783.74 154,799 154,823 170,839 v1(223,839)
  TOP w20: v1(274.72,637.63) 287.92,637.63 312.28,661.99 C1028.2@312.28,673.99
  BOTTOM w20: v1(223,839) 213.47,839 197.17,822.7 197.17,768.45 274.72,690.9 v1(274.72,637.63) 274.72,636.46 349.17,562.01 349.17,466.83 v1(473,343)
VCC2V8_DVP1: C1015.2 C1016.2 C1022.2 J19.1 J19.2 R1066.2 U71.5 | length 225.2
  TOP w10: R1066.2@952.28,465 952.28,464.6 976.68,440.2 1031.8,440.2 1055,417 1055,389 1059.85,384.15 1102.15,384.15 1112.72,394.72 C1016.2@1112.72,405.01
VCC2V8_DVP2: C1019.2 C1020.2 C1025.2 J18.24 J18.29 R1069.2 U72.5 | length 489
  TOP w10: R1069.2@1247.28,375 C1025.2@1247.28,334.99 1247.28,322.72 1255.86,314.14 1329.14,314.14 1344,329 1380,329 1392.72,341.72 C1020.2@1392.72,355.01 ; J18.24@1527.68,267.01 1527.68,297.68 1535,305 1550,305 v1(1570,325)
  BOTTOM w20: v1(1419.4,348.4) 1482.4,348.4 1494,360 1550,360 1570,340 v1(1570,325)
VCC3V3_E: C1039.2 C1040.2 C1041.2 C1042.2 L29.1 L44.2 R1170.2 | length 750.9
  TOP w15: C1041.2@3910,1122.56 3867.44,1080 3845,1080 3825,1060 3825,885 3890,820 4045,820 4070,845 4123,845 4182.72,904.72 C1039.2@4182.72,910 R1170.2@4182.72,950
VCC3V3_PHY0: C333.2 C334.2 C335.2 C359.2 C360.2 R175.2 R189.2 R190.2 R194.2 U16.11 U16.29 U16.40 | length 2127.7
  TOP w20: v1(1797.59,1961.62) 1801.79,1965.83 1954.6,1965.83 v1(1979.27,1941.16) ; v1(1953.58,2520.89) 1953.58,2528.31 2041.27,2616 2048.69,2616 2075,2642.31 R175.2@2075,2652.28 R189.2@2115,2652.28 2115,2611 2188,2538 v1(2291.38,2538)
  BOTTOM w8: 2040,2354 2040,2339 2048.13,2330.87 U16.40@2052.48,2330.87 ; 2077,2131 2089.88,2143.88 U16.29@2089.88,2167.48
  BOTTOM w15: C334.2@1952.72,2490 1977.88,2464.84 1977.88,2457.89 2018.43,2417.35 2018.43,2375.57 2040,2354
  BOTTOM w20: v1(1797.59,1961.62) 1796.42,1961.62 1746.57,2011.47 1746.57,2345.14 1799.61,2398.18 1834.33,2398.18 1850,2413.86 1850,2480 1890.89,2520.89 v1(1953.58,2520.89) 1952.17,2519.48 1952.17,2490.55 C334.2@1952.72,2490 ; v1(1979.27,1941.16) 2002.56,1964.45 C360.2@2002.56,1975 2007.78,1975 2045.85,2013.08 2045.85,2065.15 2038.28,2072.72 C333.2@2020,2072.72 2020,2092.72 2045.28,2118 2064,2118 2077,2131 ; v1(2291.38,2538) 2302.04,2538 2310.85,2529.19 2310.85,2450.85 2309.15,2449.15 2309.15,2401.42 2323.29,2387.28 C335.2@2335,2387.28
VCC3V3_PHY2: C325.2 C326.2 C327.2 C363.2 R150.2 R156.1 R157.2 R160.2 R161.1 U15.11 U15.23 U15.32 | length 2842.5
  TOP w20: R157.2@2185,2652.28 2185,2626 2211.22,2599.78 2238.77,2599.78 2273.96,2634.96 2273.96,2707.52 2322.43,2756 2514.67,2756 2597.02,2673.65 v1(2597.02,2637.01) ; v1(2688,2701) 2761.49,2774.49 2888.32,2774.49 2929.38,2815.55 2929.38,2864.62 2914,2880 R150.2@2902.72,2880 2902.72,2906.72 v1(2903.76,2907.76) ; v1(2767.5,2407.5) 2767.5,2277.14 2845,2199.64 v1(2845,2160) 2845,2148 2881.89,2111.11 2881.89,2048.11 2899.03,2030.97 2920.62,2030.97 v1(2946.65,2057)
  BOTTOM w8: C326.2@2845,2127.72 2865.63,2148.35 U15.23@2865.63,2226.26 ; U15.11@2983.74,2328.62 3022.62,2328.62
  BOTTOM w10: U15.32@2826.26,2360.12 2826.26,2375.74
  BOTTOM w20: v1(2688,2701) 2664,2677 2637.01,2677 v1(2597.02,2637.01) 2633.33,2637.01 2670,2600.34 2670,2506 2727.72,2448.28 C327.2@2727.72,2435 2740,2435 v1(2767.5,2407.5) 2791,2384 2818,2384 2826.26,2375.74 ; C326.2@2845,2127.72 v1(2845,2160) ; v1(2903.76,2907.76) 2903.76,2905.24 3103.53,2705.47 3103.53,2644.93 3109.32,2639.14 3109.32,2467.96 R160.2@3117.28,2460 ; v1(2946.65,2057) 2955,2065.35 R161.1@2955,2092.28 R156.1@2995,2092.28
VCC3V3_SD_OUT: C278.2 C287.2 J6.4 M1.9 | length 1132.9
  TOP w20: M1.9@3238.78,1074.02 3274.02,1074.02 3327,1127 3327,1172 3415,1260 v1(3485,1260)
  TOP w40: 3605,1280.85 3656.98,1280.85 3673.64,1297.5 3983.91,1297.5 4018.41,1263 v1(4023,1263) 4024.55,1264.55 v1(4054.55,1264.55) ; v1(4014.15,2203.6) 4014.15,2015.85 v1(4080,1950) v1(4080,1919)
  other v1: 3570,1315 3550,1340 3987.5,2204 4320,2750 4345,2750
VCC3V3_SPK: C207.2 C208.2 C209.2 R299.2 U25.6 U25.9
VCC3V3_SY8368: C814.1 U70.8 | length 94.1
  TOP w10: C814.1@882.72,2260 885.86,2260 929.29,2216.57 U70.8@958.82,2216.57
VCC3V3_SYS: C31.2 C32.2 C33.2 C34.2 C36.2 C284.1 C365.2 C368.2 C1032.2 C1034.2 D48.A L3.2 Q10.2 R8.2 R62.1 R240.1 R241.1 R423.1 R431.1 R1080.2 R1084.1 R1174.2 R1211.1 U59.11 | length 7137.5
  TOP w10: v1(925,1270) C31.2@925,1297.28 R8.2@965,1297.28 ; v1(2430,2280) 2430,2200 2546,2084 2546,2038.42 2680,1904.42 2680,1705 2707.5,1677.5 2707.5,1582.5 2688.82,1563.82 v1(2688.82,1482) ; v1(2565.02,2515) 2610,2515 2655,2560 2655,2595 2780,2720 2910,2720 2985.46,2795.46 v1(2985.46,2890.46) ; v1(3630,2940) 3705,2865 3705,2810 v1(3660,2765) ; v1(3835,2505) 4230,2505 v1(4255,2530) ; v1(4375,2795) 4375,2857 4385.72,2867.72 R431.1@4400,2867.72
  TOP w15: v1(215,1688) 102,1688 71.38,1657.38 71.38,1213.62 90,1195 140,1195 196.14,1138.86 678.86,1138.86 704,1164 v1(704,1276) ; 2357,1012 2357,785.79 2377.79,765 2404.59,765 v1(2423.33,746.25) ; v1(2520,646) 2611,555 2665,555 2695,525 D48.A@2720.43,525
  TOP w20: R1211.1@4785,1262.72 4785,1279.99 4811.01,1305.99 ; R241.1@5053.54,975 5053.54,972.92 5062.72,963.74 R1174.2@5062.72,925
  TOP w30: v1(4731,1359) v1(4758,1359) 4811.01,1305.99 4822,1295 4940,1295 4948,1287 5121,1287 5145,1263 5145,1030 5090,975 R241.1@5053.54,975
  BOTTOM w10: v1(2430,2280) 2450.98,2280 2565.02,2394.04 v1(2565.02,2515) ; v1(2985.46,2890.46) 3005.92,2870 3145,2870 3205,2930 3620,2930 v1(3630,2940) ; v1(3660,2765) 3645,2750 3645,2650 3790,2505 v1(3835,2505) ; v1(4255,2530) 4375,2650 v1(4375,2795)
  BOTTOM w15: v1(215,1688) 215,1692.01 265,1742.01 R62.1@265,1752.28 ; v1(2423.33,746.25) 2520,649.59 v1(2520,646)
  other v1: 1145,1200 1145,1230 1733,1238 1763,1238 1733,1268 1763,1268 1733,1298 1763,1298 660,1325 4244,1326 4299,1328 2438,1387 2468,1387 3630,1390 3660,1390 2438,1417 2468,1417 3630,1420 3660,1420 1265,1488 1265,1513 1235,1543 1265,1543
VCC5V0_HUB2: C45.1 J42.10 U6.1 | length 43.8
  TOP w40: J42.10@3567.8,3039.02 3589.02,3039.02 3605,3055
VCC5V0_HUB3: C39.1 J7.1 U4.1 | length 91.9
  TOP w20: 5174.38,2421.89 J7.1@5205,2421.89 ; 5205,2391.27 J7.1@5205,2421.89 ; 5205,2452.51 J7.1@5205,2421.89
VCC5V0_HUB4: C42.1 J8.1 U5.1 | length 91.9
  TOP w20: 5174.38,1971.89 J8.1@5205,1971.89 ; 5205,1941.27 J8.1@5205,1971.89 ; 5205,2002.51 J8.1@5205,1971.89
VCC5V_SYS: C28.2 C29.2 C30.2 C40.1 C43.1 C46.1 C77.2 C262.1 C316.2 C806.1 C811.1 C812.1 C813.1 C815.1 C870.1 C871.1 C1010.2 C1012.2 C1037.2 C1038.2 C1044.2 L33.2 Q8.2 R17.2 R450.2 R451.2 R787.1 R1063.2 R1168.2 R1209.2 R1210.2 U3.4 U4.5 U5.5 U6.5 U9.4 U29.5 U73.4 | length 546.4
  TOP w5: v1(3493,987) 3502.34,996.34 3530,996.34
  TOP w10: R787.1@770,2177.28 770,2160 772.28,2157.72 C815.1@772.28,2135.01 772.28,2042.72 800,2015 800,1870 860,1810 C1010.2@860,1739.29
  TOP w15: R1168.2@4212.72,2750 v1(4243,2750)
  other v1: 3920,850 3950,850 3980,850 3920,878.67 3949.05,878.67 3980,878.67 3477,1003 3489,1025 3512,1027 3534,1027 2985,1235 3015,1235 2985,1265 3015,1265 4875,1380 4900,1380 4925,1380 4875,1405 4900,1405 4925,1405 954.4,1490 980,1490 1005,1490 955,1515 980,1515 1005,1515 3118,1668 3145,1668 3172,1668 3118,1695 3145,1695 3172,1695 4990,1845 5015,1845 4990,1870 5015,1870 3440,2205 3470,2205 3440,2235 3470,2235 5005,2245 5030,2250 5040,2270 3845,2810 3875,2810 3905,2830 4150,2890 4115,2895 4185,2895
VCC_1V8_OUT: C92.2 J46.17 J46.18 M1.17 R13.1 R14.1 R15.1 R16.1 R382.1 R444.2 R1078.1 R1197.2 | length 6225.3
  TOP w15: R1197.2@407.28,1365 407.28,1368.94 456.67,1418.33 564.13,1418.33 587.46,1395 657.81,1395 698.74,1354.08 790.63,1354.08 ; v1(787,1145) 833.73,1191.73 833.73,1310.98 790.63,1354.08 ; v1(835.97,1577.61) 835.97,1538.42 855.61,1518.78 855.61,1419.05 790.63,1354.08 ; R16.1@865,477.72 865,503 876.86,514.86 876.86,616.18 865,628.04 v1(865,650) ; R15.1@905,477.72 906.86,479.58 906.86,633.32 v1(905,635.17) ; v1(1202.57,1118.96) 1202.57,1077.43 1230,1050 1230,1025 1242.72,1012.28 R1078.1@1255,1012.28 1255,995 1252.28,992.28 R382.1@1252.28,975 ; v1(1471,678.17) 1471,611.73 1510,572.73 R14.1@1510,472.72 R13.1@1550,472.72
  TOP w20: M1.17@3238.78,1388.98 3308.98,1388.98 v1(3385,1465)
  TOP w40: v1(1370,1605.5) 1370,1650 1388,1668 v1(1388,1825.83)
  BOTTOM w15: v1(787,1145) 918.07,1145 964.93,1098.14 1171.23,1098.14 1192.04,1118.96 v1(1202.57,1118.96) 1202.57,1129.49 1261.23,1188.15 1351.88,1188.15 1371.55,1168.48 1436.54,1168.48 1495,1110.02 1495,1034.5 1688.93,840.57 1688.93,777.45 1592.98,681.5 1502.5,681.5 1499.17,678.17 v1(1471,678.17) 1415.33,678.17 1412,681.5 1083.42,681.5 1078.42,676.5 1026.49,676.5 1000.34,650.35 947.74,650.35 930.61,633.21 906.97,633.21 v1(905,635.17) 879.83,635.17 v1(865,650)
  BOTTOM w40: 595,2425 645,2375 645,2215 623,2193 623,1962.23 641.17,1944.06 641.17,1772.4 v1(835.97,1577.61) 1043.71,1577.61 1071.61,1605.5 v1(1343.35,1605.5) v1(1370,1605.5) ; v1(1388,1825.83) v1(1420,1825.83) 1454.61,1825.83 1490.83,1789.61 1605.42,1789.61 1686.08,1708.94 1736.06,1708.94 v1(1797.5,1647.5)
  other v1: 2450,1473 2449,1500 1824.48,1620.52 308.53,2502.33 335.18,2502
VCC_3V3: C91.2 C97.2 C99.2 C102.2 C105.2 C226.2 C1013.2 C1017.2 C1033.2 C1036.2 J15.5 J46.19 J46.20 L12.1 Q10.3 R19.1 R48.2 R160.1 R194.1 R261.2 R299.1 R314.2 R318.1 R415.1 R425.1 R426.1 R437.2 R460.2 R465.1 R466.1 R1077.1 R1084.2 R1181.2 R1201.2 U11.1 U12.1 U13.1 U14.1 U42.16 U71.1 U72.1 | length 13734.3
  TOP w10: v1(4895,364) 4896,365 4998,365 5055,422 v1(5055,490)
  TOP w15: R415.1@3025,3377.72 v1(3025,3410) ; v1(3065,3305) R19.1@3065,3342.28 ; v1(4210,273.46) 4211.53,275 R425.1@4237.28,275 ; U42.16@4319.7,618.74 4341.74,618.74 4357.99,634.99 C1036.2@4377.28,634.99 ; v1(5055,1465) 5055,1480 5175,1600 5175,1685 5135,1725 v1(5130,1725)
  TOP w20: v1(3036.96,2905.03) 3052.02,2889.97 3052.02,2826.02 v1(3041,2815) ; 4311,725 4315,721 4381,721 4401,701 4401,676 4377.28,652.28 C1036.2@4377.28,634.99 ; R466.1@4600,2722.28 4612.28,2710 v1(5175,2710) ; R314.2@4887.72,2850 4906,2850 4935,2821 4976,2821 v1(4990,2835) 4990,2844 4929,2905 4929,3009 4980,3060 v1(4980,3210) ; v1(4893,1686.56) 4893.83,1685.73 4903.7,1685.73 4944.43,1645 R261.2@4962.28,1645 ; R1077.1@4895,337.72 v1(4895,364)
  TOP w30: R299.1@3980,758.54 3991.46,770 4050,770 4093,813 4135,813 4152.72,830.72 R1201.2@4171,830.72 4193.28,830.72 4206,818 v1(4206,809.17) ; R48.2@4107.72,1599 4131,1599 v1@4135,1603 ; v1(4135,1583) v1@4135,1603 ; v1(4135,1605) v1@4135,1603 ; 4146,305 4146,329.55 4253.85,437.4 4253.85,647.14 4311,704.29 4311,725 v1(4311,809.17) ; R437.2@4162.28,1599 4139,1599 v1@4135,1603 ; v1(4893,1686.56) v1(4893,1659.9) 4893,1534 4962,1465 v1(5055,1465) v1(5055,1435)
  L2-VCC w20: 243.31,1414.96 J15.5@270,1414.96 ; 270,1441.65 J15.5@270,1414.96 ; 296.69,1414.96 J15.5@270,1414.96
  L2-VCC w30: v1(1522.44,2594) 1687,2594 1701,2580 v1(2293.21,2580) 2272,2601.21 2272,2689 2336,2753 2515,2753 2599,2669 2720,2669 2835,2784 3025.34,2784 3041,2799.66 v1(3041,2815)
  BOTTOM w10: v1(5055,490) 5077.28,490 R460.2@5080,492.72
  BOTTOM w15: v1(4990,2835) 5115,2710 v1(5175,2710) 5226,2710 5250.62,2685.38 5250.62,1918 5195,1862.38 5195,1795 5130,1730 v1(5130,1725)
  BOTTOM w20: 270,1382.37 J15.5@270,1414.96 ; 270,1447.55 J15.5@270,1414.96 ; 302.59,1414.96 J15.5@270,1414.96 ; v1(2293.21,2580) 2304,2580 v1(2311,2573) ; v1(3025,3410) 3065,3370 v1(3065,3305) 3036.96,3276.96 v1(3036.96,2905.03) ; v1(4980,3210) R465.1@4980,3237.28
  BOTTOM w30: v1(346,2609.94) 1079.94,2609.94 1160,2690 1160,2724 ; v1(1101,2723) 1112,2723 1113,2724 v1(1123,2724) ; v1(1101,2746) 1115,2732 v1@1128,2732 ; L12.1@1522.44,2500 v1(1522.44,2575) v1(1522.44,2594) ; v1(2311,2573) 2311,2576 2313,2576 2343,2546 2378,2546 2435,2489 R194.1@2435,2422.72 ; v1(2857.34,171.34) v1(2880.52,171.34) 2897,171.34 ; v1(2899,186) 2897,184 2897,171.34 ; v1(3041,2815) v1(3055.5,2800.5) 3133.53,2722.47 3133.53,2657.36 3139.32,2651.57 3139.32,2487.95 3152.72,2474.55 R160.1@3152.72,2460 ; v1(4135,1605) v1(4135,1583) 4135,1574 4236.57,1472.43 4711.43,1472.43 4852,1613 4852,1618.9 v1(4893,1659.9) v1(4893,1686.56) ; v1(4206,809.17) v1(4311,809.17) ; v1(5055,1465) v1(5055,1435) 5045,1425 5045,955 4995,905 4860,905 4780,825 4780,670 4865,585 4865,446.4 4860,441.4 4860,410 4895,375 v1(4895,364) 4838.5,307.5 4663.5,307.5 4629.47,273.46 v1(4210,273.46) v1(4120,273.46) v1(4090,273.46) 3897.47,273.46 3864.83,240.83 3390.63,240.83 3321.14,171.34 2897,171.34 ; v1(1123,2724) 1123,2727 v1@1128,2732 ; v1(1123,2724) 1160,2724 ; v1@1128,2732 1160,2732 1160,2724
  other v1: 2890,400 2915,400 2890,425 2915,425 2190,508.53 2220,508.53 1425,526 1403,543 1136,570 787,592 1136,595 534,621 806,631 554,646 1110,1025 1060,1055 1090,1055 1120,1055 255,1520 285,1520 315,1520 302.8,2535 329.45,2535 345,2556.65 345,2583.31 1125,2747
VCC_3V3_OUT: M1.7 R11.1 R12.1 R383.1 R384.1 R391.2 | length 7088.4
  TOP w10: R11.1@2832.72,425 2860,425 2905,470 v1(2910,470) ; R12.1@2832.72,480 2892.72,540 v1(2905,540)
  TOP w15: v1(3845,298.33) 3854.15,298.33 3921.12,365.3 4142.85,365.3 4226.35,448.79 4226.35,658.53 4280,712.19 4280,912 4342.72,974.72 R391.2@4342.72,985
  TOP w20: v1(1823.63,2424.01) 1823.63,2401.37 1840.43,2384.57 1909.07,2384.57 1954.46,2339.17 2040.83,2339.17 2055.83,2324.17 2217.35,2324.17 2480,2061.53 2480,1984.23 2519,1945.23 2519,1896.21 2585.98,1829.22 v1(2585.98,1694.02) 2615.85,1664.15 2615.85,1617.15 2633,1600 2633,1197 2654.17,1175.83 2654.17,1089.64 2597.5,1032.96 2597.5,932.5 2557,892 2557,837 2595.87,798.13 v1(2595.87,751.59) ; v1(1877.28,2687.72) R383.1@1915,2687.72 ; v1(2905,540) 3035,540 3059.29,564.29 3059.29,610.71 3050,620 v1(3050,660) ; v1(3064.4,777.4) 3152.4,777.4 3192.5,817.5 3192.5,982.5 3205.28,995.28 M1.7@3238.78,995.28 ; v1(3291,2035) 3348.28,1977.72 R384.1@3420,1977.72
  BOTTOM w10: v1(2905,540) 2910,535 v1(2910,470)
  BOTTOM w15: v1(3050,660) 3143.67,660 3230,573.67 3230,503.01 3417.68,315.33 3707.85,315.33 3727.17,334.65 3766.13,334.65 3773.69,327.09 3821.18,327.09 3845,303.26 v1(3845,298.33)
  BOTTOM w20: v1(1823.63,2424.01) 1813.65,2433.99 1813.65,2624.09 v1(1877.28,2687.72) ; v1(2585.98,1694.02) 2647.68,1755.71 3106.71,1755.71 3225,1874 3225,1969 v1(3291,2035) ; v1(2595.87,751.59) 2704.96,642.5 2802.5,642.5 v1(2905,540) ; v1(3050,660) 3050,763 v1(3064.4,777.4)
VCC_DCIN: F3.1 F4.1 J1.4 J15.1 J43.5 J43.6 | length 1414
  TOP w20: F4.1@465.44,2957 F3.1@500,2957 F4.1@534.56,2957
  TOP w60: J1.4@126.1,3208.4 126.1,3285.1 153,3312 306,3312 359,3259 359,3138 500,2997 F3.1@500,2957
  L2-VCC w20: 79.38,1078.15 J43.6@110,1078.15 ; 79.38,1156.89 J43.5@110,1156.89 ; 87.6,3208.4 J1.4@126.1,3208.4 ; 110,1108.77 J43.6@110,1078.15 ; 110,1126.27 J43.5@110,1156.89 ; 110,1187.51 J43.5@110,1156.89 ; 126.1,3142.34 J1.4@126.1,3208.4 ; 126.1,3274.46 J1.4@126.1,3208.4 ; 140.62,1078.15 J43.6@110,1078.15 ; 140.62,1156.89 J43.5@110,1156.89 ; 164.59,3208.4 J1.4@126.1,3208.4 ; 243.31,1100 J15.1@270,1100 ; 270,1126.69 J15.1@270,1100 ; 296.69,1100 J15.1@270,1100 ; 465.44,2957 F3.1@500,2957 ; 500,2922.44 F3.1@500,2957 ; 500,2991.56 F3.1@500,2957 ; 534.56,2957 F3.1@500,2957
  other v1: 415,2945 415,2975 419,3003 445,3005 475,3005 505,3005
VCC_DMIC: C227.2 J45.1 R318.2
VCC_LEDA+: C89.2 C90.2 C1031.2 D18.C J46.23 J46.24 U10.5 | length 607.6
  BOTTOM w20: D18.C@140,2297.44 171.56,2329 179.56,2321 332,2321 357,2296 357,2081 332,2056 263,2056 250,2043 U10.5@250,2016.85
  other v1: 186,2325 199.14,2348.27 200,2375 200,2405 208,2616 195,2636
VCC_LEDK-: J46.21 J46.22 R84.2 R412.2 R413.2 | length 416.3
  TOP w10: v1(215,2575) 204.17,2564.17 204.17,2493.83 223,2475 223,2253.95 v1(220,2250.95)
  BOTTOM w10: v1(220,2250.95) 245.12,2225.83 276.89,2225.83 R84.2@285,2217.72
  other v1: 193,2575
VCC_M2: C289.2 C291.2 C292.2 C293.2 C294.2 C295.2 C301.2 C348.2 C349.2 C350.2 C351.2 C352.2 J27.2 J27.4 J27.12 J27.14 J27.16 J27.18 J27.70 J27.72 J27.74 L29.2
  other v1: 3765.43,1113.94 3765.6,1140.59 3765.6,1167.25 3765.5,1193.9 3765.19,1220.55 3765.6,1247.31 3804.63,1490.33 3834.63,1490.33 3864.63,1490.33 3804.63,1516.98 3834.63,1516.98 3864.63,1516.98 3822.71,1773.48 3795,1775 3795.48,1799.52 3820,1800 3769.4,1805
VCC_OUT: C264.2 C1046.2 C1047.2 J44.1 J54.1 J55.1 J56.1 R366.2 R1077.2 | length 1474
  TOP w20: 4799.53,180 J44.1@4840,180 ; 4840,139.53 J44.1@4840,180 ; 4840,220.47 J44.1@4840,180 ; 4880.47,180 J44.1@4840,180
  BOTTOM w20: 3526.27,117.72 J55.1@3556.89,117.72 ; 3556.89,87.09 J55.1@3556.89,117.72 ; 3556.89,148.34 J55.1@3556.89,117.72 ; 3587.51,117.72 J55.1@3556.89,117.72 ; 4799.53,180 J44.1@4840,180 ; 4840,139.53 J44.1@4840,180 ; 4880.47,180 J44.1@4840,180 ; v1(4900,255) 5050,405 5220,405 5255,440 5255,935 5207.28,982.72 J56.1@5207.28,1056.89
  other v1: 3463,181 3493,181 3523,181 4875,230 4900,230
VCC_RMII: C159.2 C164.2 C338.2 L11.1 L12.2 R195.2 R204.2 R205.1 R207.1 R212.2 R217.2 R219.1 R1200.2 U17.14 | length 2208.4
  TOP w10: R1200.2@1305,2067.28 1315,2057.28 1315,1985 1356.65,1943.35 v1(1389.99,1943.35)
  TOP w15: R219.1@1347.72,2795 v1(1377.67,2795)
  TOP w20: v1(1389.99,1943.35) v1(1390,2015) 1427.5,2052.5 1427.5,2388 1435.05,2395.55 1435.05,2456.05 1512.54,2533.54 v1(1576,2533.54) ; v1(1584.74,2411.46) 1584.74,2382.62 v1(1594.8,2372.56) 1587.99,2372.56 1575.43,2360 1575.43,2280.82 1585.42,2270.83 1608.98,2270.83 1624.81,2255 v1(1645,2255)
  BOTTOM w10: U17.14@1439.5,2230.45 1469.55,2230.45 1474.99,2225.01
  BOTTOM w15: v1(1377.67,2795) 1396.89,2795 1632.44,2559.45 C159.2@1632.44,2500 ; R212.2@1562.72,2350 1572.24,2350 v1(1594.8,2372.56)
  BOTTOM w20: R205.1@1245,2042.28 R207.1@1285,2042.28 1285,1984 1325.65,1943.35 v1(1389.99,1943.35) ; v1(1390,2015) R204.2@1390,2042.28 ; 1474.99,2225.01 C338.2@1527.28,2225.01 1527.28,2212.14 1541.42,2198 1613,2198 1645,2230 v1(1645,2255) 1624,2276 1599,2276 1570,2305 R195.2@1562.72,2305
VCC_SIM: C65.2 C314.2 C315.2 J11.C1 R52.2 R53.2 R440.2 U8.8 | length 553.3
  TOP w20: 4505,2350 4505,2230.79 4520,2215.79 v1(4520,2189.4) R440.2@4520,2162.72 ; v1(4717.72,2091) R53.2@4717.72,2125 R52.2@4717.72,2165
  BOTTOM w20: v1(4520,2189.4) 4520,2145 4570,2095 4643.48,2095 4672.3,2066.17 4694.17,2066.17 4717.72,2089.72 v1(4717.72,2091)
  other v1: 4583,2329 4614,2329 4316,2366 4346,2366
VCC_SYS: C1.1 C2.2 C3.2 C807.2 C808.2 C809.2 D1.C D2.C R783.1 U70.4 U70.5 U70.6 | length 274.2
  TOP w12: R783.1@847.28,2120 847.28,2111.72 860.85,2098.15 901.99,2098.15 v1(908.84,2105)
  BOTTOM w12: v1(908.84,2105) 908.84,2183.84 965,2240 v1(965,2277.68)
VCC_TP: C285.2 R421.2 R422.2 R423.2 R448.2 R449.2 R1197.1 U59.1 | length 232.4
  TOP w10: R449.2@407.28,1205 R422.2@407.28,1245 R421.2@407.28,1285 407.28,1285.4 442.72,1320.84 C285.2@442.72,1325
  TOP w20: 507,1395 555.64,1395 585.64,1365 R423.2@592.28,1365
VCCA_RMII: C160.2 C336.2 C337.2 L11.2 U17.7 U17.30 | length 717.1
  TOP w20: v1(1215,2275) 1215,2144.34 1244.3,2115.03 1265.7,2115.03 1285.7,2135.03 1285.7,2251.14 1401.93,2367.37 v1(1401.93,2415)
  BOTTOM w10: C336.2@1162.72,2305 1172.72,2315 1211.11,2315 1236.56,2289.55 U17.30@1250.5,2289.55
  BOTTOM w20: C336.2@1162.72,2305 1172.72,2295 1195,2295 v1(1215,2275)
VCCIO4_IN: C271.2 M1.31 R384.2 | length 243.4
  TOP w20: M1.31@3238.78,1940.16 3359.84,1940.16 3402.28,1897.72 C271.2@3419.99,1897.72 ; C271.2@3419.99,1897.72 R384.2@3420,1942.28
VCCIO5_IN: C270.2 M1.76 R383.2 | length 252
  TOP w20: R383.2@1915,2652.28 C270.2@1955,2652.28 1955,2635 1969.72,2620.28 1969.72,2579.81 1927.76,2537.84 M1.76@1927.76,2463.78
VCCIO6_IN: C269.2 M1.116 R382.2 | length 499.8
  TOP w15: R382.2@1287.72,975 C269.2@1287.72,940.01 1305.01,940.01 1326.75,961.75 1326.75,1188.1 1409.52,1270.87 M1.116@1482.87,1270.87
VCCIO_PHY0: C358.2 C361.2 R178.2 R182.2 R185.2 R188.2 R191.2 U16.28 | length 1979.3
  TOP w15: v1(1715.77,1943.79) 1760.31,1988.33 1975.46,1988.33 1988.79,1975 v1(2149.14,1975)
  TOP w20: v1(2149.14,1975) v1(2252.87,1975.01) 2257.48,1975.01 v1(2289.43,1943.05) 2309.31,1923.17 2320.68,1923.17 v1(2338.82,1905.03) 2357,1886.85 2357,1816.98 v1(2393.45,1780.53)
  BOTTOM w8: 2105.63,2133 U16.28@2105.63,2167.48
  BOTTOM w15: R188.2@1687.72,1970 1702.72,1955 1704.56,1955 v1(1715.77,1943.79) ; v1(2289.43,1943.05) 2289.43,1957.15 R185.2@2297.28,1965 ; v1(2338.82,1905.03) 2370,1936.2 R178.2@2370,2037.28 ; R191.2@2372.72,2265 2395.07,2265 2470.97,2189.11 2470.97,2173.78 2517.5,2127.24 2517.5,1904.58 v1(2393.45,1780.53)
  BOTTOM w20: 2105.63,2133 2105.63,2121.63 2075,2091 C361.2@2075,2072.72 2092.28,2072.72 2104.15,2060.85 2104.15,1988.41 C358.2@2117.56,1975 v1(2149.14,1975) ; v1(2252.87,1975.01) 2252.87,1979.68 2280,2006.81 R182.2@2280,2037.28
VCCIO_WL: C342.2 C366.2 R240.2 U18.22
